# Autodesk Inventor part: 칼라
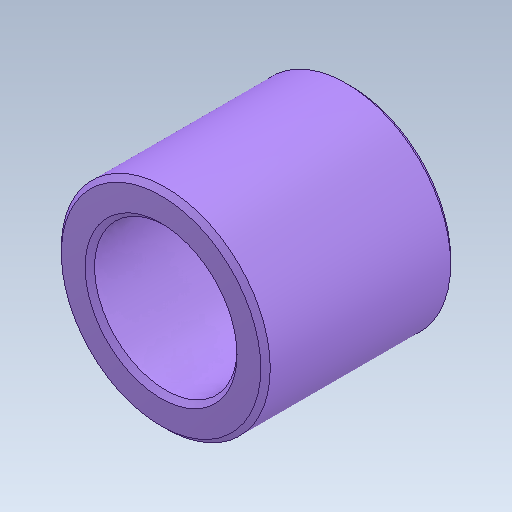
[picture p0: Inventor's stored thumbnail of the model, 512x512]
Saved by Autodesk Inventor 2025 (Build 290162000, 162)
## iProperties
Created: 2024-07
Part Number: 칼라
Material: 스테인리스강
Document SubType Name: Modeling
Designer: 미서니
Density: 8.08 g/cm^3
Appearance: 기본값
Author: jhkim
Sending System: Autodesk Inventor 2025
Preprocessor: ST-DEVELOPER v20
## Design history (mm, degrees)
feature "솔리드1"
node "솔리드2"
